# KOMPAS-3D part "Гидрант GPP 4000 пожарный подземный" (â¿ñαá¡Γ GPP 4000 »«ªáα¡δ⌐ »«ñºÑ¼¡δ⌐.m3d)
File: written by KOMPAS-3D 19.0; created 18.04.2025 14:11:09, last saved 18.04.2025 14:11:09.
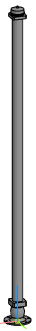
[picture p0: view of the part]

Document properties: Полное имя файла: E:\Dendor Работа Сачек\3D для проекитирвщиков\11.1 Тип GPP. Гидрант пожарный подземный\stp_Тип GPP. 750-6000 Гидрант пожарный подземный\Гидрант GPP 4000 пожарный подземный.m3d

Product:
- Part/product: Гидрант GPP 4000 пожарный подземный

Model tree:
1. Операция без истории:1  (labels: Гидрант GPP 4000 пожарный подземный)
